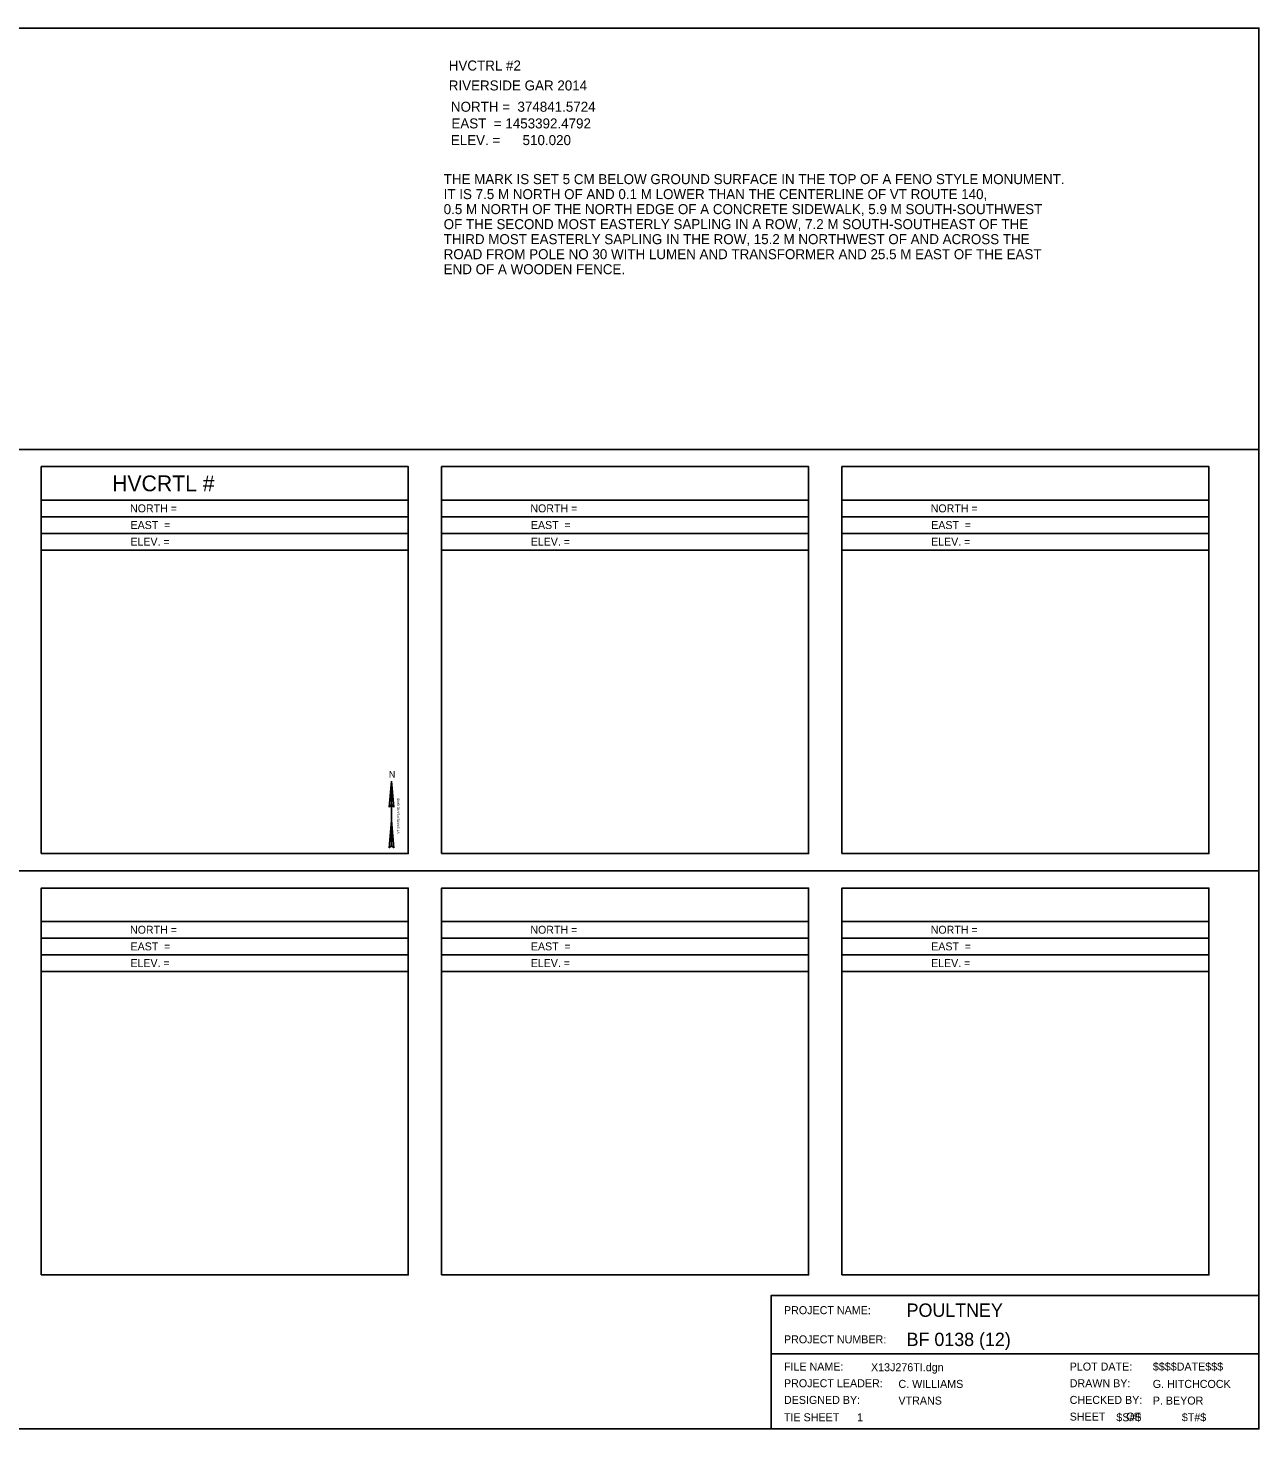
# Model space of a CAD drawing. Extents: x 1454446 to 1455086, y 375501 to 375921.
# Drawn here: x 1454717.4 to 1455086.4, y 375500.6 to 375920.6 of the extents above; entities that cross this region are included whole.
import ezdxf

# ---------------------------------------------------------------- set-up
doc = ezdxf.new("R2010")
doc.units = 0
for name, color, linetype in [('Default', 7, 'Continuous'), ('NBL1', 7, 'Continuous'), ('NBL2', 7, 'Continuous'), ('NNA_P', 7, 'Continuous')]:
    doc.layers.add(name, color=color, linetype=linetype)

msp = doc.modelspace()

# ---------------------------------------------------------------- linework, layer by layer
at = {"layer": 'NBL1'}
msp.add_line((1454940.13, 375523.1), (1455086.38, 375523.1), dxfattribs=at)
msp.add_lwpolyline([(1454446.38, 375500.6), (1455086.38, 375500.6), (1455086.38, 375920.6), (1454446.38, 375920.6)], close=True, dxfattribs=at)
msp.add_lwpolyline([(1455086.38, 375540.6), (1454940.13, 375540.6), (1454940.13, 375500.6)], dxfattribs=at)
at = {"layer": 'NBL2'}
for p, q in [((1454446.38, 375794.27), (1455086.38, 375794.27)), ((1454831.37, 375779.1), (1454721.37, 375779.1)), ((1454951.37, 375779.1), (1454841.37, 375779.1)), ((1455071.37, 375779.1), (1454961.37, 375779.1)), ((1454831.37, 375774.1), (1454721.37, 375774.1)), ((1454951.37, 375774.1), (1454841.37, 375774.1)), ((1455071.37, 375774.1), (1454961.37, 375774.1)), ((1454831.37, 375769.1), (1454721.37, 375769.1)), ((1454951.37, 375769.1), (1454841.37, 375769.1)), ((1455071.37, 375769.1), (1454961.37, 375769.1)), ((1454831.37, 375764.1), (1454721.37, 375764.1)), ((1454951.37, 375764.1), (1454841.37, 375764.1)), ((1455071.37, 375764.1), (1454961.37, 375764.1)), ((1454446.38, 375667.93), (1455086.38, 375667.93)), ((1454831.37, 375652.77), (1454721.37, 375652.77)), ((1454951.37, 375652.77), (1454841.37, 375652.77)), ((1455071.37, 375652.77), (1454961.37, 375652.77)), ((1454831.37, 375647.77), (1454721.37, 375647.77)), ((1454951.37, 375647.77), (1454841.37, 375647.77)), ((1455071.37, 375647.77), (1454961.37, 375647.77)), ((1454831.37, 375642.77), (1454721.37, 375642.77)), ((1454951.37, 375642.77), (1454841.37, 375642.77)), ((1455071.37, 375642.77), (1454961.37, 375642.77)), ((1454831.37, 375637.77), (1454721.37, 375637.77)), ((1454951.37, 375637.77), (1454841.37, 375637.77)), ((1455071.37, 375637.77), (1454961.37, 375637.77))]:
    msp.add_line(p, q, dxfattribs=at)
for points in [[(1454721.37, 375673.1), (1454831.37, 375673.1), (1454831.37, 375789.1), (1454721.37, 375789.1)], [(1454841.37, 375673.1), (1454951.37, 375673.1), (1454951.37, 375789.1), (1454841.37, 375789.1)], [(1454961.37, 375673.1), (1455071.37, 375673.1), (1455071.37, 375789.1), (1454961.37, 375789.1)], [(1454721.37, 375546.77), (1454831.37, 375546.77), (1454831.37, 375662.77), (1454721.37, 375662.77)], [(1454841.37, 375546.77), (1454951.37, 375546.77), (1454951.37, 375662.77), (1454841.37, 375662.77)], [(1454961.37, 375546.77), (1455071.37, 375546.77), (1455071.37, 375662.77), (1454961.37, 375662.77)]]:
    msp.add_lwpolyline(points, close=True, dxfattribs=at)
at = {"layer": 'NNA_P'}
for p, q in [((1454825.65, 375687.06), (1454826.34, 375694.85)), ((1454826.34, 375675.47), (1454826.34, 375694.85)), ((1454827.03, 375687.06), (1454826.34, 375694.85)), ((1454825.65, 375687.06), (1454826.34, 375687.82)), ((1454827.04, 375687.06), (1454826.34, 375687.82)), ((1454826.35, 375683), (1454825.62, 375674.83)), ((1454826.34, 375683), (1454827.06, 375674.83)), ((1454826.34, 375675.47), (1454825.62, 375674.83)), ((1454826.34, 375675.47), (1454827.06, 375674.83))]:
    msp.add_line(p, q, dxfattribs=at)

# ---------------------------------------------------------------- texts
at = {"layer": 'Default'}
for s, p in [('THE MARK IS SET 5 CM BELOW GROUND SURFACE IN THE TOP OF A FENO STYLE MONUMENT.', (1454841.99, 375873.8)), ('IT IS 7.5 M NORTH OF AND 0.1 M LOWER THAN THE CENTERLINE OF VT ROUTE 140,', (1454841.99, 375869.3)), ('0.5 M NORTH OF THE NORTH EDGE OF A CONCRETE SIDEWALK, 5.9 M SOUTH-SOUTHWEST ', (1454841.99, 375864.8)), ('OF THE SECOND MOST EASTERLY SAPLING IN A ROW, 7.2 M SOUTH-SOUTHEAST OF THE ', (1454841.99, 375860.3)), ('THIRD MOST EASTERLY SAPLING IN THE ROW, 15.2 M NORTHWEST OF AND ACROSS THE ', (1454841.99, 375855.8)), ('ROAD FROM POLE NO 30 WITH LUMEN AND TRANSFORMER AND 25.5 M EAST OF THE EAST ', (1454841.99, 375851.3)), ('END OF A WOODEN FENCE.', (1454841.99, 375846.8))]:
    msp.add_text(s, height=3, dxfattribs=at).set_placement(p)
at = {"layer": 'NBL1'}
for s, height, p in [('PROJECT NAME:', 2.4, (1454943.99, 375535.02)), ('POULTNEY                  ', 4, (1454980.76, 375534.22)), ('PROJECT NUMBER:', 2.4, (1454943.99, 375526.27)), ('BF 0138 (12)              ', 4, (1454980.76, 375525.47)), ('FILE NAME:', 2.4, (1454943.99, 375518.11)), ('     X13J276TI.dgn        ', 2.4, (1454965.62, 375517.91)), ('PLOT DATE:', 2.4, (1455029.64, 375518.11)), ('$$$$DATE$$$', 2.4, (1455054.57, 375518.11)), ('PROJECT LEADER:', 2.4, (1454943.99, 375513.11)), ('C. WILLIAMS         ', 2.4, (1454978.31, 375512.91)), ('DRAWN BY:', 2.4, (1455029.64, 375513.11)), ('G. HITCHCOCK ', 2.4, (1455054.54, 375512.91)), ('DESIGNED BY:', 2.4, (1454943.99, 375508.11)), ('VTRANS              ', 2.4, (1454978.31, 375507.91)), ('CHECKED BY:', 2.4, (1455029.64, 375508.11)), ('P. BEYOR     ', 2.4, (1455054.54, 375507.91)), ('TIE SHEET      1                  ', 2.4, (1454943.99, 375502.91)), ('SHEET       OF', 2.4, (1455029.64, 375503.11)), ('$S#$ ', 2.4, (1455043.62, 375502.91)), ('$T#$   ', 2.4, (1455063.24, 375502.91))]:
    msp.add_text(s, height=height, dxfattribs=at).set_placement(p)
at = {"layer": 'NBL2'}
for s, height, p in [('HVCTRL #2           ', 3, (1454843.52, 375907.86)), ('RIVERSIDE GAR 2014  ', 3, (1454843.52, 375901.88)), ('NORTH =  374841.5724', 3, (1454844.16, 375895.5)), ('EAST  = 1453392.4792', 3, (1454844.31, 375890.5)), ('ELEV. =      510.020', 3, (1454844.13, 375885.5)), ('      HVCRTL #     ', 4.75, (1454732.02, 375781.72)), ('NORTH =             ', 2.375, (1454747.99, 375775.41)), ('NORTH =             ', 2.375, (1454867.99, 375775.41)), ('NORTH =             ', 2.375, (1454987.99, 375775.41)), ('EAST  =             ', 2.375, (1454748.14, 375770.41)), ('EAST  =             ', 2.375, (1454868.14, 375770.41)), ('EAST  =             ', 2.375, (1454988.14, 375770.41)), ('ELEV. =             ', 2.375, (1454748.1, 375765.41)), ('ELEV. =             ', 2.375, (1454868.1, 375765.41)), ('ELEV. =             ', 2.375, (1454988.1, 375765.41)), ('NORTH =             ', 2.375, (1454747.99, 375649.08)), ('NORTH =             ', 2.375, (1454867.99, 375649.08)), ('NORTH =             ', 2.375, (1454987.99, 375649.08)), ('EAST  =             ', 2.375, (1454748.14, 375644.08)), ('EAST  =             ', 2.375, (1454868.14, 375644.08)), ('EAST  =             ', 2.375, (1454988.14, 375644.08)), ('ELEV. =             ', 2.375, (1454748.1, 375639.08)), ('ELEV. =             ', 2.375, (1454868.1, 375639.08)), ('ELEV. =             ', 2.375, (1454988.1, 375639.08))]:
    msp.add_text(s, height=height, dxfattribs=at).set_placement(p)
at = {"layer": 'NNA_P'}
msp.add_text('N', height=1.97, dxfattribs=at).set_placement((1454825.58, 375695.86))
msp.add_text('VT STATE PLANE GRID', height=0.7, rotation=90.0204, dxfattribs=at).set_placement((1454828.69, 375679.04))

doc.saveas('drawing.dxf')
